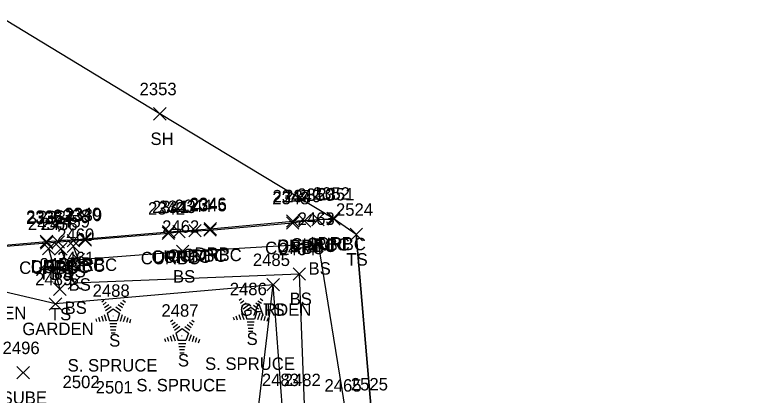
# Model space of a CAD drawing. Extents: x 1623612 to 1625808, y 621345 to 627748.
# Drawn here: x 1624481.9 to 1624601.5, y 626697.4 to 626758.5 of the extents above; entities that cross this region are included whole.
import ezdxf

# ---------------------------------------------------------------- set-up
doc = ezdxf.new("R2010")
doc.units = 0
for name, color, linetype in [('L_A', 7, 'Continuous'), ('L_C', 7, 'Continuous'), ('L_I', 7, 'Continuous'), ('L_TIC', 7, 'Continuous'), ('LAPB', 7, 'Continuous'), ('LELB', 7, 'Continuous'), ('LSOGP', 7, 'Continuous'), ('LTC', 7, 'Continuous'), ('R_A', 7, 'Continuous'), ('R_I', 7, 'Continuous'), ('R_TIC', 7, 'Continuous'), ('RC', 7, 'Continuous'), ('RDP', 7, 'Continuous'), ('U_A', 7, 'Continuous'), ('U_I', 7, 'Continuous'), ('U_TIC', 7, 'Continuous')]:
    doc.layers.add(name, color=color, linetype=linetype)

msp = doc.modelspace()

# ---------------------------------------------------------------- linework, layer by layer
at = {"layer": 'L_TIC'}
for points in [[(1624504.16, 626741.57), (1624506.16, 626743.57)], [(1624506.16, 626741.57), (1624504.16, 626743.57)], [(1624535.67, 626722.2), (1624537.67, 626724.2)], [(1624537.67, 626722.2), (1624535.67, 626724.2)], [(1624529.57, 626720.74), (1624531.57, 626722.74)], [(1624531.57, 626720.74), (1624529.57, 626722.74)], [(1624486.31, 626719.92), (1624488.31, 626721.92)], [(1624488.31, 626719.92), (1624486.31, 626721.92)], [(1624488.27, 626719.89), (1624490.27, 626721.89)], [(1624490.27, 626719.89), (1624488.27, 626721.89)], [(1624490.26, 626720.31), (1624492.26, 626722.31)], [(1624492.26, 626720.31), (1624490.26, 626722.31)], [(1624507.82, 626719.47), (1624509.82, 626721.47)], [(1624509.82, 626719.47), (1624507.82, 626721.47)], [(1624491.07, 626718.16), (1624493.07, 626720.16)], [(1624493.07, 626718.16), (1624491.07, 626720.16)], [(1624526.53, 626715.86), (1624528.53, 626717.86)], [(1624528.53, 626715.86), (1624526.53, 626717.86)], [(1624490.43, 626714.43), (1624492.43, 626716.43)], [(1624492.43, 626714.43), (1624490.43, 626716.43)], [(1624488.11, 626713.41), (1624490.11, 626715.41)], [(1624490.11, 626713.41), (1624488.11, 626715.41)], [(1624522.34, 626714.13), (1624524.34, 626716.13)], [(1624524.34, 626714.13), (1624522.34, 626716.13)], [(1624522.34, 626714.13), (1624524.34, 626716.13)], [(1624524.34, 626714.13), (1624522.34, 626716.13)], [(1624487.42, 626711.03), (1624489.42, 626713.03)], [(1624489.42, 626711.03), (1624487.42, 626713.03)]]:
    msp.add_lwpolyline(points, dxfattribs=at)
at = {"layer": 'LAPB'}
msp.add_lwpolyline([(1624519.69, 626684.58), (1624523.34, 626715.13), (1624488.42, 626712.03), (1624477.63, 626714.58), (1624464.93, 626721.39), (1624461.33, 626722.07), (1624457.88, 626718.13), (1624464.59, 626710.11), (1624484.4, 626690.25), (1624505.15, 626670.18), (1624528.47, 626653.34), (1624551.05, 626637.75), (1624575.65, 626620.57), (1624601.46, 626602.9)], dxfattribs=at)
at = {"layer": 'LELB'}
for points in [[(1624536.67, 626723.2), (1624539.06, 626695.14), (1624541.99, 626679.69), (1624547.43, 626666.77), (1624555.92, 626657.11), (1624569.13, 626651.09), (1624583.16, 626648.53), (1624599.82, 626654.21)], [(1624491.26, 626721.31), (1624492.07, 626719.16), (1624508.82, 626720.47), (1624530.57, 626721.74), (1624534.88, 626694.95), (1624538.16, 626676.05), (1624549.52, 626657.18), (1624566.25, 626646.71), (1624582.7, 626641.97), (1624580.46, 626638.41), (1624566.04, 626640.55), (1624551.55, 626648.76), (1624540.93, 626658.22), (1624533.96, 626671.15), (1624530.07, 626682.34), (1624528.29, 626695.83)], [(1624487.31, 626720.92), (1624489.11, 626714.41)], [(1624489.27, 626720.89), (1624491.43, 626715.43), (1624527.53, 626716.86), (1624528.29, 626695.83)], [(1624580.46, 626638.41), (1624564.23, 626639.32), (1624549.58, 626647.72), (1624538.33, 626656.77), (1624530.6, 626670.09), (1624527.19, 626681.4), (1624524.78, 626695.84), (1624523.34, 626715.13)]]:
    msp.add_lwpolyline(points, dxfattribs=at)
at = {"layer": 'LSOGP'}
msp.add_lwpolyline([(1624539.06, 626695.14), (1624536.67, 626723.2), (1624533.11, 626725.67), (1624532.96, 626725.78), (1624505.16, 626742.57), (1624478.95, 626758.47)], dxfattribs=at)
at = {"layer": 'LTC'}
for p, q in [((1624517.88, 626712.65), (1624518.23, 626712.91)), ((1624521.27, 626712.89), (1624521.69, 626712.59)), ((1624495.83, 626712.39), (1624496.18, 626712.65)), ((1624496.04, 626711.92), (1624496.56, 626712.31)), ((1624496.25, 626711.46), (1624496.95, 626711.97)), ((1624496.45, 626710.99), (1624497.33, 626711.63)), ((1624498.48, 626711.93), (1624499.16, 626711.44)), ((1624498.85, 626712.28), (1624499.4, 626711.88)), ((1624499.22, 626712.63), (1624499.64, 626712.33)), ((1624518.09, 626712.18), (1624518.61, 626712.57)), ((1624518.3, 626711.72), (1624519, 626712.23)), ((1624518.5, 626711.25), (1624519.38, 626711.89)), ((1624520.16, 626711.85), (1624520.97, 626711.26)), ((1624520.53, 626712.19), (1624521.21, 626711.7)), ((1624520.9, 626712.54), (1624521.45, 626712.14)), ((1624496.68, 626710.54), (1624497.69, 626711.27)), ((1624496.68, 626710.54), (1624497.07, 626709.34)), ((1624497.69, 626711.27), (1624498.69, 626710.55)), ((1624498.11, 626711.59), (1624498.92, 626711)), ((1624498.69, 626710.55), (1624498.3, 626709.34)), ((1624518.27, 626710.58), (1624518.61, 626709.56)), ((1624518.73, 626710.8), (1624519.74, 626711.53)), ((1624518.73, 626710.8), (1624519.12, 626709.6)), ((1624519.74, 626711.53), (1624520.74, 626710.81)), ((1624520.74, 626710.81), (1624520.35, 626709.6)), ((1624521.18, 626710.54), (1624520.84, 626709.5)), ((1624494.86, 626709.67), (1624495.01, 626709.2)), ((1624495.31, 626709.89), (1624495.53, 626709.23)), ((1624495.77, 626710.1), (1624496.04, 626709.27)), ((1624496.22, 626710.32), (1624496.56, 626709.3)), ((1624498.3, 626709.34), (1624497.07, 626709.34)), ((1624499.13, 626710.28), (1624498.79, 626709.24)), ((1624499.57, 626710.03), (1624499.28, 626709.14)), ((1624500.01, 626709.78), (1624499.78, 626709.05)), ((1624500.46, 626709.53), (1624500.27, 626708.95)), ((1624506.86, 626709.2), (1624507.22, 626709.46)), ((1624510.26, 626709.44), (1624510.68, 626709.14)), ((1624516.91, 626709.93), (1624517.06, 626709.46)), ((1624517.36, 626710.15), (1624517.58, 626709.49)), ((1624517.82, 626710.36), (1624518.09, 626709.53)), ((1624520.35, 626709.6), (1624519.12, 626709.6)), ((1624521.62, 626710.29), (1624521.33, 626709.4)), ((1624522.06, 626710.04), (1624521.83, 626709.31)), ((1624522.51, 626709.79), (1624522.32, 626709.21)), ((1624498.26, 626708.84), (1624497.11, 626708.84)), ((1624498.17, 626708.34), (1624497.19, 626708.34)), ((1624507.07, 626708.73), (1624507.6, 626709.12)), ((1624507.28, 626708.27), (1624507.99, 626708.78)), ((1624507.49, 626707.8), (1624508.37, 626708.44)), ((1624507.72, 626707.35), (1624508.73, 626708.08)), ((1624508.73, 626708.08), (1624509.73, 626707.36)), ((1624509.15, 626708.4), (1624509.96, 626707.81)), ((1624509.52, 626708.74), (1624510.2, 626708.25)), ((1624509.89, 626709.09), (1624510.44, 626708.69)), ((1624520.31, 626709.1), (1624519.16, 626709.1)), ((1624520.22, 626708.6), (1624519.24, 626708.6)), ((1624520.14, 626708.1), (1624519.31, 626708.1)), ((1624498.09, 626707.84), (1624497.26, 626707.84)), ((1624498.01, 626707.34), (1624497.33, 626707.34)), ((1624506.81, 626706.91), (1624507.08, 626706.08)), ((1624507.26, 626707.13), (1624507.59, 626706.11)), ((1624507.72, 626707.35), (1624508.1, 626706.15)), ((1624509.73, 626707.36), (1624509.34, 626706.15)), ((1624510.16, 626707.09), (1624509.83, 626706.05)), ((1624520.06, 626707.6), (1624519.38, 626707.6)), ((1624505.9, 626706.48), (1624506.05, 626706.01)), ((1624506.35, 626706.7), (1624506.56, 626706.04)), ((1624509.34, 626706.15), (1624508.1, 626706.15)), ((1624509.3, 626705.65), (1624508.15, 626705.65)), ((1624510.61, 626706.84), (1624510.32, 626705.95)), ((1624511.05, 626706.59), (1624510.82, 626705.86)), ((1624511.5, 626706.34), (1624511.31, 626705.76)), ((1624509.21, 626705.15), (1624508.22, 626705.15)), ((1624509.13, 626704.65), (1624508.3, 626704.65)), ((1624509.05, 626704.15), (1624508.37, 626704.15))]:
    msp.add_line(p, q, dxfattribs=at)
at = {"layer": 'R_TIC'}
for points in [[(1624525.46, 626724.04), (1624527.46, 626726.04)], [(1624527.46, 626724.04), (1624525.46, 626726.04)], [(1624525.49, 626724.35), (1624527.49, 626726.35)], [(1624527.49, 626724.35), (1624525.49, 626726.35)], [(1624527.37, 626724.38), (1624529.37, 626726.38)], [(1624529.37, 626724.38), (1624527.37, 626726.38)], [(1624529.53, 626724.6), (1624531.53, 626726.6)], [(1624531.53, 626724.6), (1624529.53, 626726.6)], [(1624531.96, 626724.78), (1624533.96, 626726.78)], [(1624533.96, 626724.78), (1624531.96, 626726.78)], [(1624532.11, 626724.67), (1624534.11, 626726.67)], [(1624534.11, 626724.67), (1624532.11, 626726.67)], [(1624509.78, 626722.8), (1624511.78, 626724.8)], [(1624511.78, 626722.8), (1624509.78, 626724.8)], [(1624512.2, 626722.91), (1624514.2, 626724.91)], [(1624514.2, 626722.91), (1624512.2, 626724.91)], [(1624512.24, 626723.11), (1624514.24, 626725.11)], [(1624514.24, 626723.11), (1624512.24, 626725.11)], [(1624505.52, 626722.4), (1624507.52, 626724.4)], [(1624507.52, 626722.4), (1624505.52, 626724.4)], [(1624505.59, 626722.62), (1624507.59, 626724.62)], [(1624507.59, 626722.62), (1624505.59, 626724.62)], [(1624507.22, 626722.64), (1624509.22, 626724.64)], [(1624509.22, 626722.64), (1624507.22, 626724.64)], [(1624485.96, 626721.07), (1624487.96, 626723.07)], [(1624487.96, 626721.07), (1624485.96, 626723.07)], [(1624486.01, 626720.86), (1624488.01, 626722.86)], [(1624488.01, 626720.86), (1624486.01, 626722.86)], [(1624487.88, 626720.99), (1624489.88, 626722.99)], [(1624489.88, 626720.99), (1624487.88, 626722.99)], [(1624490.29, 626721.2), (1624492.29, 626723.2)], [(1624492.29, 626721.2), (1624490.29, 626723.2)], [(1624492.15, 626721.5), (1624494.15, 626723.5)], [(1624494.15, 626721.5), (1624492.15, 626723.5)], [(1624492.21, 626721.34), (1624494.21, 626723.34)], [(1624494.21, 626721.34), (1624492.21, 626723.34)]]:
    msp.add_lwpolyline(points, dxfattribs=at)
at = {"layer": 'RC'}
msp.add_lwpolyline([(1624473.3, 626720.74), (1624487.01, 626721.86), (1624488.88, 626721.99), (1624491.29, 626722.2), (1624493.21, 626722.34), (1624506.52, 626723.4), (1624508.22, 626723.64), (1624510.78, 626723.8), (1624513.2, 626723.91), (1624526.46, 626725.04), (1624528.37, 626725.38), (1624530.53, 626725.6), (1624533.11, 626725.67)], dxfattribs=at)
at = {"layer": 'RDP'}
msp.add_lwpolyline([(1624473.4, 626720.88), (1624486.96, 626722.07), (1624493.15, 626722.5), (1624506.59, 626723.62), (1624513.24, 626724.11), (1624526.49, 626725.35), (1624532.96, 626725.78)], dxfattribs=at)
at = {"layer": 'U_TIC'}
for points in [[(1624482.23, 626699.98), (1624484.23, 626701.98)], [(1624484.23, 626699.98), (1624482.23, 626701.98)]]:
    msp.add_lwpolyline(points, dxfattribs=at)

# ---------------------------------------------------------------- texts
at = {"layer": 'L_A'}
for s, p in [('SH', (1624503.65, 626737.57)), ('TS', (1624535.08, 626718.2)), ('TS', (1624485.72, 626715.92)), ('BS', (1624487.71, 626715.89)), ('BS', (1624489.7, 626716.31)), ('BS', (1624529.01, 626716.74)), ('BS', (1624507.27, 626715.47)), ('BS', (1624490.51, 626714.16)), ('BS', (1624525.97, 626711.86)), ('BS', (1624489.87, 626710.43)), ('GARDEN', (1624518.01, 626710.13)), ('TS', (1624521.75, 626710.13)), ('GARDEN', (1624472.3, 626709.58)), ('TS', (1624487.52, 626709.41)), ('GARDEN', (1624483.09, 626707.03)), ('S', (1624497.02, 626705.18)), ('S', (1624519.07, 626705.44)), ('S', (1624508.05, 626701.99))]:
    msp.add_text(s, height=2, dxfattribs=at).set_placement(p)
at = {"layer": 'L_C'}
for p in [(1624512.41, 626701.44), (1624490.36, 626701.18), (1624501.39, 626697.99)]:
    msp.add_text('S. SPRUCE', height=2, dxfattribs=at).set_placement(p)
at = {"layer": 'L_I'}
for s, p in [('2353', (1624501.9, 626745.57)), ('2524', (1624533.41, 626726.2)), ('2459', (1624487.99, 626724.31)), ('2463', (1624527.26, 626724.74)), ('2456', (1624483.99, 626723.92)), ('2458', (1624486.01, 626723.89)), ('2462', (1624505.52, 626723.47)), ('2460', (1624488.68, 626722.16)), ('2464', (1624524.22, 626719.86)), ('2461', (1624488.69, 626718.43)), ('2485', (1624520.08, 626718.13)), ('2485', (1624520.08, 626718.13)), ('2457', (1624485.85, 626717.41)), ('2489', (1624485.15, 626715.03)), ('2488', (1624494.37, 626713.18)), ('2486', (1624516.37, 626713.44)), ('2487', (1624505.41, 626709.99)), ('2483', (1624521.52, 626698.84)), ('2482', (1624525.03, 626698.83)), ('2482', (1624525.03, 626698.83)), ('2502', (1624489.54, 626698.51)), ('2501', (1624494.86, 626697.65)), ('2465', (1624531.57, 626697.95)), ('2525', (1624535.8, 626698.14))]:
    msp.add_text(s, height=2, dxfattribs=at).set_placement(p)
at = {"layer": 'LTC'}
for p in [(1624497.57, 626710.29), (1624519.62, 626710.55), (1624508.61, 626707.1)]:
    msp.add_text('.', height=1.04, rotation=270, dxfattribs=at).set_placement(p)
at = {"layer": 'R_A'}
for s, p in [('CURBC', (1624523.95, 626720.38)), ('CURBC', (1624526.12, 626720.6)), ('CURBC', (1624528.7, 626720.67)), ('DRP', (1624530.45, 626720.78)), ('CURBC', (1624522.04, 626720.04)), ('DRP', (1624523.98, 626720.35)), ('CURBC', (1624502.1, 626718.4)), ('CURBC', (1624503.81, 626718.64)), ('DRP', (1624504.08, 626718.62)), ('CURBC', (1624506.36, 626718.8)), ('CURBC', (1624508.78, 626718.91)), ('DRP', (1624510.72, 626719.11)), ('CURBC', (1624482.59, 626716.86)), ('CURBC', (1624484.46, 626716.99)), ('DRP', (1624484.44, 626717.07)), ('CURBC', (1624486.87, 626717.2)), ('CURBC', (1624488.79, 626717.34)), ('DRP', (1624490.64, 626717.5))]:
    msp.add_text(s, height=2, dxfattribs=at).set_placement(p)
at = {"layer": 'R_I'}
for s, p in [('2352', (1624529.7, 626728.78)), ('2348', (1624523.2, 626728.04)), ('2347', (1624523.23, 626728.35)), ('2349', (1624525.1, 626728.38)), ('2350', (1624527.19, 626728.6)), ('2351', (1624530.42, 626728.67)), ('2342', (1624503.26, 626726.4)), ('2341', (1624503.9, 626726.62)), ('2343', (1624504.96, 626726.64)), ('2344', (1624507.52, 626726.8)), ('2346', (1624509.92, 626727.11)), ('2345', (1624509.94, 626726.91)), ('2338', (1624488.03, 626725.2)), ('2340', (1624489.81, 626725.5)), ('2339', (1624489.94, 626725.34)), ('2335', (1624483.7, 626725.07)), ('2336', (1624483.69, 626724.86)), ('2337', (1624485.62, 626724.99))]:
    msp.add_text(s, height=2, dxfattribs=at).set_placement(p)
at = {"layer": 'U_A'}
msp.add_text('SUBE', height=2, dxfattribs=at).set_placement((1624479.77, 626695.98))
at = {"layer": 'U_I'}
msp.add_text('2496', height=2, dxfattribs=at).set_placement((1624479.92, 626703.98))

doc.saveas('drawing.dxf')
